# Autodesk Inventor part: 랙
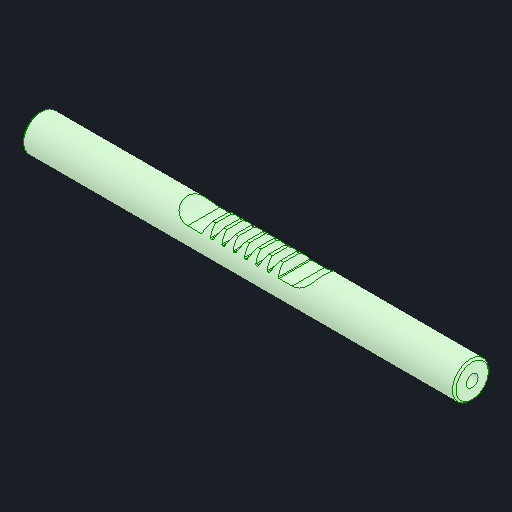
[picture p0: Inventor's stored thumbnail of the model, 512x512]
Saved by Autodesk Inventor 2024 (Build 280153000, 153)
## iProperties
Created: 2024-05
Part Number: 랙
Material: 강철, 탄소
Document SubType Name: Modeling
Designer: kh_501
Density: 7.85 g/cm^3
Appearance: 기본값
Author: jhkim
Sending System: Autodesk Inventor 2025
Preprocessor: ST-DEVELOPER v20
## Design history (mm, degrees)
node "랙1"
node "솔리드2"
node "솔리드1"
